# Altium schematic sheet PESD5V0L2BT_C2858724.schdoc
size 127 x 101 mm
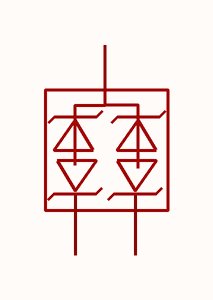
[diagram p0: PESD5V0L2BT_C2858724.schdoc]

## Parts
D?  pesd5v0l2bt  [SOT-23-3_L2.9-W1.3-P0.95-LS2.4-BR]  (value not drawn)

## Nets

Not connected (* = marked no-connect by the designer): D? 1 2 3

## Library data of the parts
D? = pesd5v0l2bt: 极性:双向;反向截止电压(Vrwm):5V;钳位电压:10V;峰值脉冲电流(Ipp):10A;击穿电压:8.6V;; Manufacturer: TECH PUBLIC(台舟); Symbol: PESD5V0L2BT_C2858724; AddInBom: yes; ModelId: c62791f0466c4ae2a892c056b845b0ca; ModelName: SOT-23-3P_L2.9-W1.3-H1.0-LS2.4-P0.95; ModelTransform: 98.425,114.173,0,180,0,0,0.0005,-0.0005,0; Polarity: 双向; Reverse Stand-Off Voltage (Vrwm): 5V; Clamping Voltage: 10V; Peak Pulse Current (Ipp): 10A; Voltage - Breakdown: 8.6V; Reverse Leakage Current (Ir): 60nA; Number of Channels: 双路; level of protection: IEC 61000-4-2；IEC 61000-4-4；IEC 61000-4-5; Type: ESD; Junction Capacitance: 15pF；7pF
